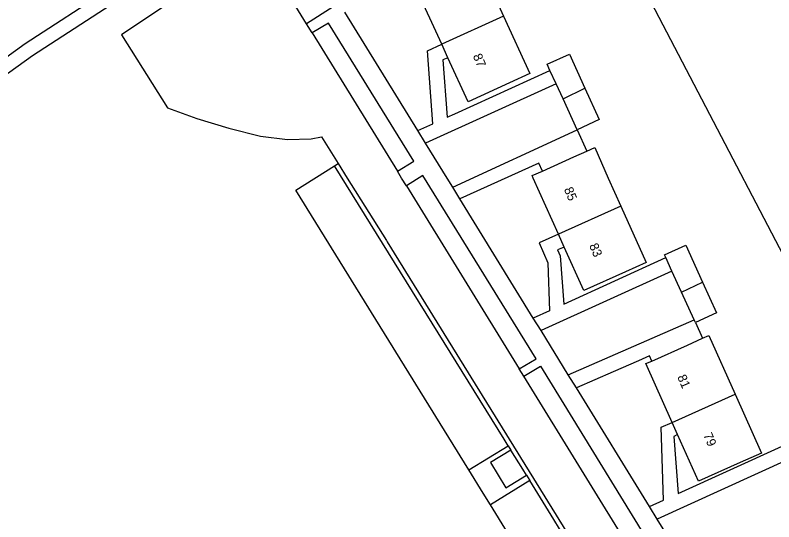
# Model space of a CAD drawing. Extents: x 158132 to 159658, y 385257 to 387209.
# Drawn here: x 158545 to 158628, y 386962.3 to 387017.8 of the extents above; entities that cross this region are included whole.
import ezdxf

# ---------------------------------------------------------------- set-up
doc = ezdxf.new("R2010")
doc.units = 0
for name, color, linetype in [('IMGEO_Fietspad_gesloten', 7, 'Continuous'), ('IMGEO_Gemengd_bos', 7, 'Continuous'), ('IMGEO_Groenvoorziening', 7, 'Continuous'), ('IMGEO_Pand', 7, 'Continuous'), ('IMGEO_Pand_nummerreeks', 7, 'Continuous'), ('IMGEO_Parkeervlak_open', 7, 'Continuous'), ('IMGEO_Rijbaan_lokaal_open', 7, 'Continuous'), ('IMGEO_Voetpad_gesloten', 7, 'Continuous'), ('IMGEO_Voetpad_open', 7, 'Continuous')]:
    doc.layers.add(name, color=color, linetype=linetype)

msp = doc.modelspace()

# ---------------------------------------------------------------- linework, layer by layer
at = {"layer": 'IMGEO_Fietspad_gesloten'}
msp.add_lwpolyline([(158823.804, 387176.598), (158776.889, 387150.893), (158732.48, 387123.894), (158722.886, 387118.521), (158715.758, 387114.904), (158709.569, 387111.62), (158675.022, 387091.93), (158640.944, 387072.387), (158595.958, 387046.323), (158573.791, 387032.697), (158546.099, 387014.697), (158529.924, 387003.032), (158525.945, 387000), (158514.127, 386990.649), (158513.131, 386989.793), (158506.548, 386984.134), (158500, 386978.134), (158499.211, 386977.385), (158490.608, 386969.265)], dxfattribs=at)
at = {"layer": 'IMGEO_Gemengd_bos'}
msp.add_lwpolyline([(158648.608, 386908.461), (158679.256, 386924.451), (158659.443, 386961.72), (158647.808, 386955.65), (158601.872, 387043.698)], dxfattribs=at)
at = {"layer": 'IMGEO_Groenvoorziening'}
msp.add_lwpolyline([(158597.011, 386964.203), (158596.221, 386965.488), (158594.652, 386968.028)], dxfattribs=at)
at = {"layer": 'IMGEO_Pand'}
for points in [[(158591.688, 387014.656), (158588.816, 387020.952), (158593.366, 387023.028), (158595.581, 387024.038), (158598.453, 387017.743)], [(158598.453, 387017.743), (158591.688, 387014.656)], [(158598.453, 387017.743), (158601.325, 387011.448), (158599.109, 387010.437), (158594.56, 387008.361), (158592.361, 387013.18)], [(158592.361, 387013.18), (158591.688, 387014.656)], [(158603.528, 387011.792), (158603.223, 387012.461), (158605.65, 387013.568), (158607.357, 387009.825)], [(158604.196, 387010.329), (158603.528, 387011.792)], [(158604.953, 387008.668), (158604.196, 387010.329)], [(158604.953, 387008.668), (158607.357, 387009.825)], [(158607.357, 387009.825), (158608.919, 387006.402), (158606.492, 387005.295)], [(158606.492, 387005.295), (158604.953, 387008.668)], [(158602.716, 387000.769), (158606.144, 387002.307), (158607.549, 387002.937)], [(158607.549, 387002.937), (158608.419, 387003.327), (158609.911, 387000), (158611.297, 386996.91)], [(158604.459, 386993.843), (158601.698, 387000), (158601.581, 387000.26), (158602.716, 387000.769)], [(158611.297, 386996.91), (158604.459, 386993.843)], [(158611.297, 386996.91), (158614.059, 386990.753), (158611.783, 386989.732), (158607.22, 386987.686), (158605.087, 386992.443)], [(158605.087, 386992.443), (158604.459, 386993.843)], [(158616.21, 386991.278), (158616.074, 386991.576), (158618.383, 386992.629), (158620.23, 386988.581)], [(158616.878, 386989.814), (158616.21, 386991.278)], [(158617.938, 386987.489), (158616.878, 386989.814)], [(158617.938, 386987.489), (158620.23, 386988.581)], [(158620.23, 386988.581), (158621.754, 386985.241), (158619.445, 386984.187)], [(158619.323, 386984.455), (158617.938, 386987.489)], [(158619.445, 386984.187), (158619.323, 386984.455)], [(158614.66, 386979.954), (158618.583, 386981.709), (158620.238, 386982.449)], [(158620.238, 386982.449), (158620.917, 386982.753), (158623.799, 386976.31)], [(158616.9, 386973.224), (158614.018, 386979.667), (158614.66, 386979.954)], [(158616.9, 386973.224), (158623.799, 386976.31)], [(158623.799, 386976.31), (158626.681, 386969.867), (158624.347, 386968.823), (158619.782, 386966.781), (158617.495, 386971.894)], [(158617.495, 386971.894), (158616.9, 386973.224)]]:
    msp.add_lwpolyline(points, dxfattribs=at)
at = {"layer": 'IMGEO_Parkeervlak_open'}
for points in [[(158594.652, 386968.028), (158575.724, 386998.679), (158579.928, 387001.317)], [(158594.652, 386968.028), (158598.964, 386970.684)], [(158601.32, 386966.859), (158597.011, 386964.203)], [(158619.872, 386926.996), (158597.011, 386964.203)]]:
    msp.add_lwpolyline(points, dxfattribs=at)
at = {"layer": 'IMGEO_Rijbaan_lokaal_open'}
for points in [[(158576.888, 387016.901), (158571.433, 387025.779), (158569.559, 387024.621)], [(158567.571, 387023.393), (158567.705, 387023.128), (158556.617, 387015.67), (158561.678, 387007.692), (158564.887, 387006.535), (158568.36, 387005.469), (158571.856, 387004.58), (158574.806, 387004.228), (158577.392, 387004.289), (158578.517, 387004.505), (158580.351, 387001.582)], [(158577.496, 387015.894), (158576.888, 387016.901)], [(158577.496, 387015.894), (158586.825, 387000.753)], [(158579.928, 387001.317), (158580.351, 387001.582)], [(158598.964, 386970.684), (158598.515, 386971.412), (158579.928, 387001.317)], [(158580.351, 387001.582), (158581.344, 387000), (158585.638, 386993.157), (158585.718, 386993.027), (158634.345, 386914.283)], [(158587.806, 386999.158), (158587.289, 387000), (158586.825, 387000.753)], [(158587.806, 386999.158), (158600.17, 386979.092)], [(158600.655, 386978.306), (158600.17, 386979.092)], [(158625.647, 386937.743), (158613.486, 386957.482), (158613, 386958.271), (158600.655, 386978.306)], [(158598.964, 386970.684), (158599.256, 386970.209)], [(158600.952, 386967.456), (158600.556, 386968.099), (158599.256, 386970.209)], [(158600.952, 386967.456), (158601.32, 386966.859)], [(158624.242, 386929.684), (158615.464, 386943.914), (158604.579, 386961.572), (158603.949, 386962.593), (158601.32, 386966.859)]]:
    msp.add_lwpolyline(points, dxfattribs=at)
at = {"layer": 'IMGEO_Voetpad_gesloten'}
for points in [[(158572.64, 387030.179), (158579.815, 387018.756), (158576.888, 387016.901)], [(158490.266, 386966.826), (158500, 386976.111), (158500.231, 386976.331), (158507.529, 386983.023), (158514.053, 386988.611), (158515.068, 386989.481), (158528.384, 387000), (158530.815, 387001.855), (158546.88, 387013.42), (158565.976, 387025.844)], [(158589.055, 387005.205), (158581.083, 387018.152)], [(158586.825, 387000.753), (158588.643, 387001.829), (158579.302, 387016.974), (158577.496, 387015.894)], [(158589.912, 387003.814), (158589.055, 387005.205)], [(158592.885, 386998.985), (158592.26, 387000), (158589.912, 387003.814)], [(158600.17, 386979.092), (158602.004, 386980.189), (158589.605, 387000.261), (158587.806, 386999.158)], [(158593.653, 386997.738), (158592.885, 386998.985)], [(158601.705, 386984.662), (158593.653, 386997.738)], [(158602.555, 386983.281), (158601.705, 386984.662)], [(158605.533, 386978.445), (158602.555, 386983.281)], [(158600.655, 386978.306), (158602.475, 386979.395), (158614.784, 386959.361), (158615.262, 386958.579), (158627.405, 386938.838), (158625.647, 386937.743)], [(158606.417, 386977.009), (158605.533, 386978.445)], [(158614.421, 386964.012), (158606.417, 386977.009)], [(158615.271, 386962.631), (158614.421, 386964.012)], [(158618.31, 386957.695), (158615.271, 386962.631)]]:
    msp.add_lwpolyline(points, dxfattribs=at)
at = {"layer": 'IMGEO_Voetpad_open'}
for points in [[(158589.055, 387005.205), (158590.707, 387005.945), (158590.117, 387013.939), (158591.688, 387014.656)], [(158592.361, 387013.18), (158591.818, 387012.932), (158592.281, 387006.663), (158593.11, 387007.041), (158603.528, 387011.792)], [(158604.196, 387010.329), (158589.912, 387003.814)], [(158592.885, 386998.985), (158606.492, 387005.295)], [(158606.492, 387005.295), (158607.549, 387002.937)], [(158602.716, 387000.769), (158602.322, 387001.627), (158593.653, 386997.738)], [(158604.459, 386993.843), (158602.336, 386992.891), (158603.31, 386990.722), (158603.468, 386985.466), (158601.705, 386984.662)], [(158605.087, 386992.443), (158604.364, 386992.119), (158604.651, 386991.478), (158605.042, 386986.184), (158616.21, 386991.278)], [(158616.878, 386989.814), (158602.555, 386983.281)], [(158605.533, 386978.445), (158619.323, 386984.455)], [(158619.445, 386984.187), (158620.238, 386982.449)], [(158614.66, 386979.954), (158614.412, 386980.508), (158613.216, 386979.973), (158610.46, 386978.772), (158606.417, 386977.009)], [(158614.421, 386964.012), (158615.967, 386964.717), (158615.706, 386972.729), (158616.9, 386973.224)], [(158617.495, 386971.894), (158617.078, 386971.704), (158617.54, 386965.435), (158628.951, 386970.639)], [(158599.256, 386970.209), (158597.014, 386968.825), (158598.71, 386966.079), (158600.952, 386967.456)], [(158629.609, 386969.171), (158615.271, 386962.631)]]:
    msp.add_lwpolyline(points, dxfattribs=at)

# ---------------------------------------------------------------- texts
at = {"layer": 'IMGEO_Pand_nummerreeks'}
for s, p in [('87', (158595.065, 387013.38)), ('85', (158605.033, 386998.765)), ('83', (158607.794, 386992.608)), ('81', (158617.442, 386978.22)), ('79', (158620.291, 386971.856))]:
    msp.add_text(s, height=1, rotation=292.9754, dxfattribs=at).set_placement(p)

doc.saveas('drawing.dxf')
